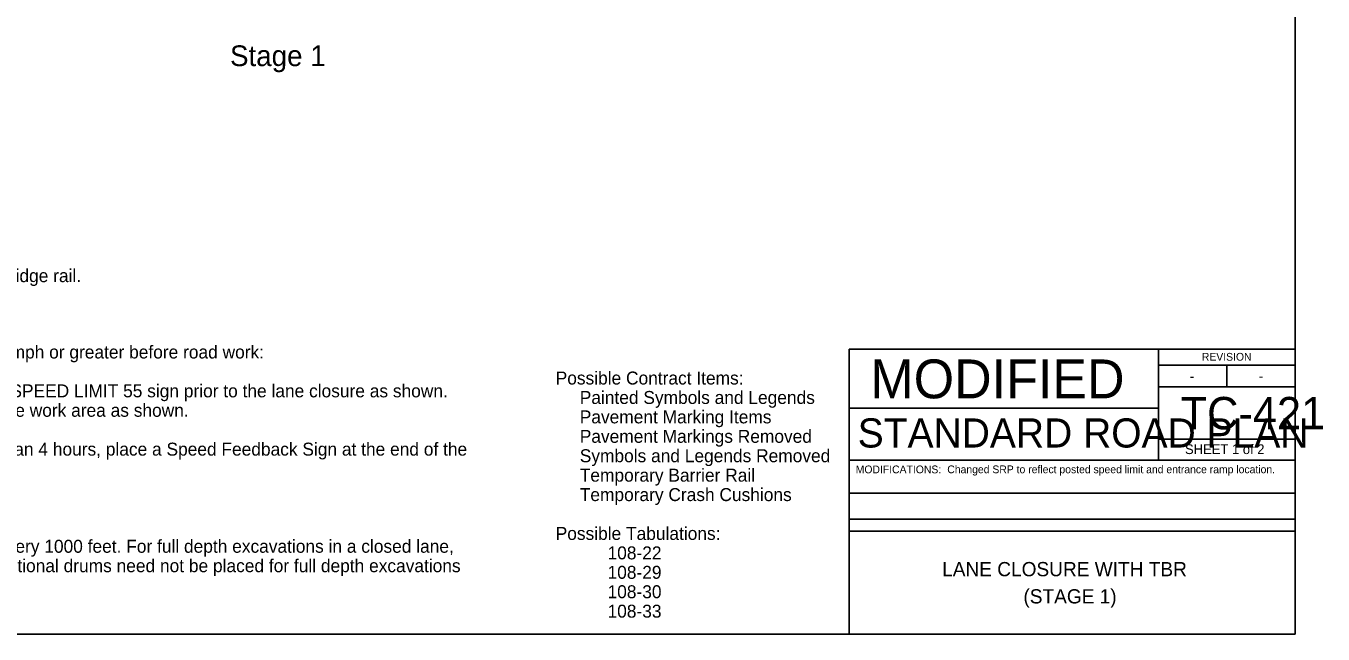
# Model space of a CAD drawing. Extents: x 10133 to 2270741, y 5363 to 1733450.
# Drawn here: x 25709 to 27711, y 7924 to 8863 of the extents above; entities that cross this region are included whole.
import ezdxf

# ---------------------------------------------------------------- set-up
doc = ezdxf.new("R2010")
doc.units = 0
for name, color, linetype in [('dsnStdDimension', 7, 'Continuous'), ('dsnStdShading', 7, 'Continuous'), ('dsnStdTable', 7, 'Continuous'), ('SheetBorder', 7, 'Continuous')]:
    doc.layers.add(name, color=color, linetype=linetype)

msp = doc.modelspace()

# ---------------------------------------------------------------- linework, layer by layer
at = {"layer": 'dsnStdDimension'}
for p, q in [((27456.6, 8364), (27456.6, 8272.7)), ((27456.6, 8339.1), (27667.5, 8339.1)), ((27562.1, 8339.1), (27562.1, 8305.9)), ((27456.6, 8305.9), (27667.5, 8305.9)), ((26979.5, 8272.7), (27456.6, 8272.7)), ((27456.6, 8272.7), (27456.6, 8192.7)), ((27667.5, 8224.9), (27456.6, 8224.9)), ((26979.5, 8192.7), (27667.5, 8192.7)), ((26979.5, 8141.7), (27667.5, 8141.7)), ((26979.5, 8101.7), (27667.5, 8101.7)), ((26979.5, 8082.7), (27667.5, 8082.7))]:
    msp.add_line(p, q, dxfattribs=at)
msp.add_lwpolyline([(26979.5, 8364), (27667.5, 8364), (27667.5, 7924), (26979.5, 7924)], close=True, dxfattribs=at)
at = {"layer": 'SheetBorder'}
msp.add_lwpolyline([(24532.5, 9944), (27667.5, 9944), (27667.5, 7924), (24532.5, 7924)], close=True, dxfattribs=at)

# ---------------------------------------------------------------- texts
at = {"layer": 'dsnStdDimension'}
for s, height, p in [('Stage 1', 32, (26024.1, 8801.1)), ('REVISION', 12, (27523.6, 8346.2)), ('-', 15, (27505.1, 8314.7)), ('-', 15, (27611.6, 8315.1)), ('TC-421', 50, (27490.9, 8240.2)), ('STANDARD ROAD PLAN', 45.001, (26992.6, 8212.1)), ('SHEET 1 of 2', 15, (27497.6, 8202)), ('Changed SRP to reflect posted speed limit and entrance ramp location.', 12, (27130.8, 8172.4)), ('LANE CLOSURE WITH TBR', 22, (27122.9, 8013.3)), ('(STAGE 1)', 22, (27248.3, 7971.3))]:
    msp.add_text(s, height=height, dxfattribs=at).set_placement(p)
at = {"layer": 'dsnStdShading'}
msp.add_text('MODIFICATIONS:', height=12, dxfattribs=at).set_placement((26989.5, 8172.3))
at = {"layer": 'dsnStdTable'}
for s, p in [('Place Concrete Barrier Markers at 10 ft C/C on bridge rail.', (25107.6, 8467.5)), ('For roadways with a posted speed limit of 60 mph or greater before road work:', (25148.9, 8349.6)), ('Possible Contract Items:', (26526.6, 8309.4)), ('Place SPEED LIMIT AHEAD sign and SPEED LIMIT 55 sign prior to the lane closure as shown. ', (25228.9, 8289.6)), ('     Painted Symbols and Legends', (26526.6, 8279.4)), ('Place SPEED LIMIT65 or 70 beyond the work area as shown.', (25228.9, 8259.6)), ('     Pavement Marking Items', (26526.6, 8249.4)), ('     Pavement Markings Removed', (26526.6, 8219.4)), ('For traffic control zones lasting more than 4 hours, place a Speed Feedback Sign at the end of the ', (25228.9, 8199.6)), ('     Symbols and Legends Removed', (26526.6, 8189.4)), ('     Temporary Barrier Rail', (26526.6, 8159.4)), ('     Temporary Crash Cushions', (26526.6, 8129.4)), ('Possible Tabulations:', (26526.6, 8069.4)), ('For lanes closed to traffic, place two drums every 1000 feet. For full depth excavations in a closed lane, ', (25148.9, 8049.6)), ('108-22', (26606.6, 8039.4)), ('place two drums in front of each location. Additional drums need not be placed for full depth excavations ', (25148.9, 8019.6)), ('108-29', (26606.6, 8009.4)), ('108-30', (26606.6, 7979.4)), ('108-33', (26606.6, 7949.4))]:
    msp.add_text(s, height=20, dxfattribs=at).set_placement(p)
at = {"layer": 'SheetBorder'}
msp.add_text('MODIFIED', height=60, dxfattribs=at).set_placement((27012.1, 8288.1))

doc.saveas('drawing.dxf')
